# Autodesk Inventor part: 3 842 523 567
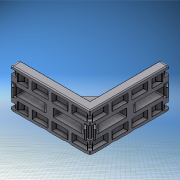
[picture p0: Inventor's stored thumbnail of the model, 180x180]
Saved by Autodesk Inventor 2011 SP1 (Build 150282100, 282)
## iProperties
Created: 2011-02
Part Number: 3 842 523 567
Description: GUSSET 45X90
Document SubType Name: Modeling
Designer: SRW
Stock Number: 3 842 523 567
Density: 2.71 g/cm^3
Material: Aluminum-6061
Mass: 177.789 g
Surface Area: 268.344 cm^2
Volume: 65.6046 cm^3
Author: SRW
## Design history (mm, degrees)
feature "Base1"
body "Solid1"
